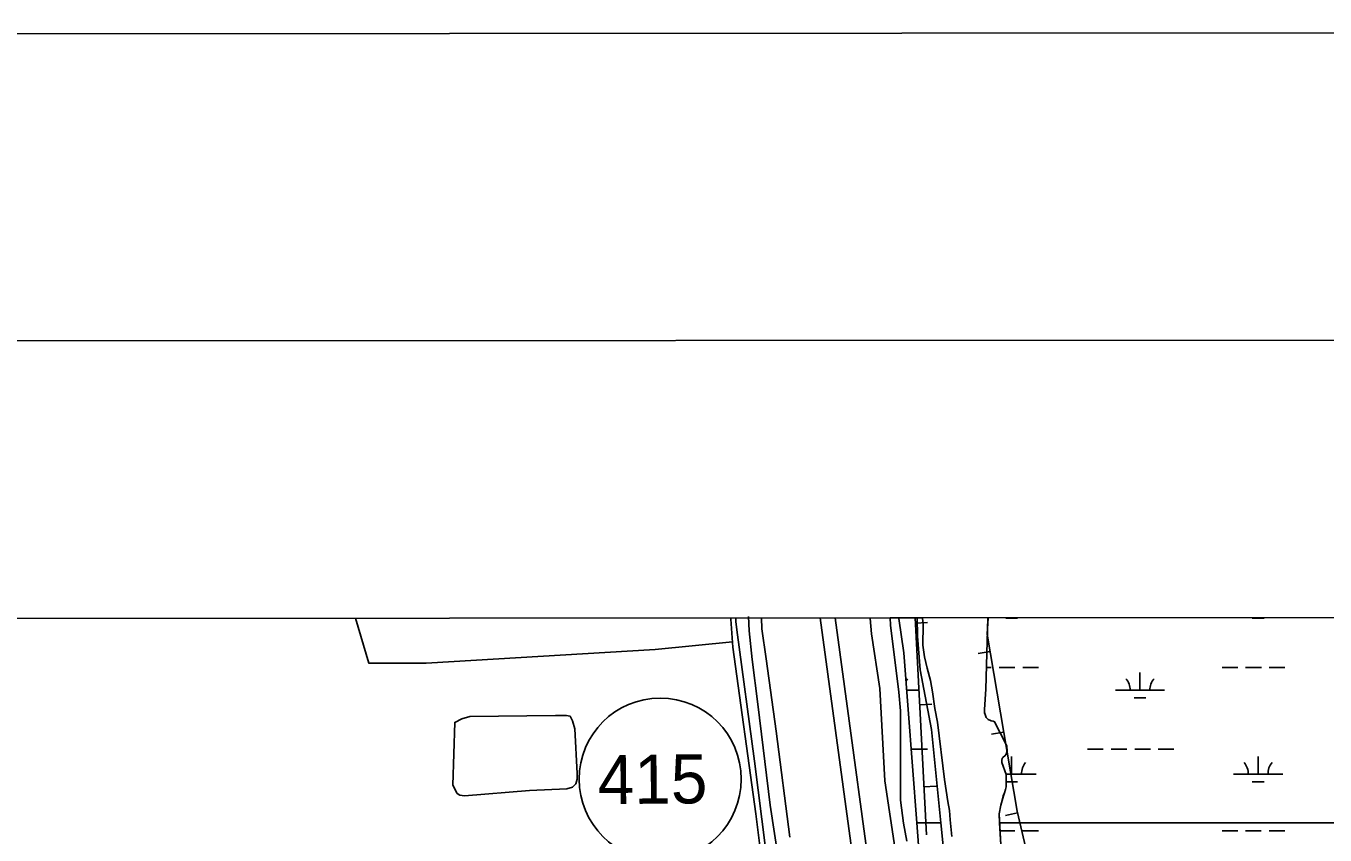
# Model space of a CAD drawing. Extents: x 3281947 to 3319794, y 715894 to 741249.
# Drawn here: x 3291976 to 3294621, y 739019 to 740665 of the extents above; entities that cross this region are included whole.
import ezdxf

# ---------------------------------------------------------------- set-up
doc = ezdxf.new("R2010")
doc.units = 0
for name, color, linetype in [('G-ANNO-NPLT', 7, 'Continuous'), ('V-ANNO-SYMB', 7, 'Continuous'), ('V-BORW-LINE', 7, 'Continuous'), ('V-DTCH-CNTR', 7, 'Continuous'), ('V-GRID-FRAM', 7, 'Continuous'), ('V-LEVE-TOET', 7, 'Continuous'), ('V-ROAD-CNTR', 7, 'Continuous'), ('V-ROAD-IDEN', 7, 'Continuous'), ('V-SITE-VEGE', 7, 'Continuous'), ('V-SURV-LINE', 7, 'Continuous'), ('V-TOPO-SHOR', 7, 'Continuous'), ('V-WETL-SWMP', 7, 'Continuous')]:
    doc.layers.add(name, color=color, linetype=linetype)

msp = doc.modelspace()

# ---------------------------------------------------------------- linework, layer by layer
at = {"layer": 'G-ANNO-NPLT'}
msp.add_lwpolyline([(3282544.2, 716477.2), (3319210.9, 716498.6), (3319196.8, 740665.2), (3282530.2, 740643.9)], close=True, dxfattribs=at)
at = {"layer": 'V-ANNO-SYMB'}
msp.add_lwpolyline([(3285294, 717103.9), (3318377.2, 717123.1), (3318363.9, 740039.7), (3285280.7, 740020.4), (3285294, 717103.9)], dxfattribs=at)
at = {"layer": 'V-BORW-LINE'}
for p, q in [((3293786.5, 739449.7), (3293811.4, 739451)), ((3293938.8, 739392.4), (3293914.1, 739388.3)), ((3293795.1, 739283.3), (3293820.1, 739284.6)), ((3293966.4, 739228.2), (3293941.8, 739224)), ((3293803.8, 739116.9), (3293828.7, 739118.2)), ((3293994.3, 739063.9), (3293970, 739058.2))]:
    msp.add_line(p, q, dxfattribs=at)
for points in [[(3293785.9, 739460.7), (3293808.9, 739018.8)], [(3293808.9, 739018.8), (3293785.9, 739460.7)], [(3294013.5, 738982.8), (3293993.5, 739067.2), (3293932.9, 739427.6), (3293934.7, 739460.7)], [(3293934.7, 739460.7), (3293932.9, 739427.6), (3293993.5, 739067.2), (3294013.5, 738982.8)]]:
    msp.add_lwpolyline(points, dxfattribs=at)
at = {"layer": 'V-DTCH-CNTR'}
for points in [[(3291851.2, 738680.1), (3292201.5, 738700.7), (3292515.1, 738720.8), (3292753.9, 738735.4), (3292868.1, 738749.9), (3292880.2, 738749.6), (3292899.7, 738743.2), (3292915.8, 738736.3), (3292940.9, 738730.1), (3293230, 738752.2), (3293464.6, 738774), (3293472.9, 738774.8), (3293478.7, 738776.1), (3293483.2, 738777.9), (3293489.3, 738781.9), (3293491.4, 738786.1), (3293493.4, 738791.7), (3293494.4, 738800.9), (3293492.7, 738812.4), (3293462, 739061.4), (3293414.9, 739400.7), (3293410.8, 739457.9), (3293410.8, 739460.4)], [(3293414.1, 739411.7), (3293257.1, 739396.1), (3292790.8, 739368.2), (3292674, 739368.3), (3292646.8, 739460)]]:
    msp.add_lwpolyline(points, dxfattribs=at)
at = {"layer": 'V-GRID-FRAM'}
msp.add_lwpolyline([(3286080.7, 739456.2), (3317564.6, 739474.5), (3317583.1, 721289.3), (3286083.3, 721271), (3286080.7, 739456.2)], dxfattribs=at)
at = {"layer": 'V-LEVE-TOET'}
for points in [[(3293473.1, 739460.5), (3293474, 739438.1), (3293482.5, 739377.3), (3293503.2, 739229.7), (3293530.8, 739013.9)], [(3293768.3, 738836), (3293724.7, 739129.2), (3293714.4, 739316.8), (3293697.3, 739428.1), (3293694.3, 739459.2), (3293694.3, 739460.6)]]:
    msp.add_lwpolyline(points, dxfattribs=at)
at = {"layer": 'V-ROAD-CNTR'}
msp.add_lwpolyline([(3293526.2, 738848.4), (3293491.1, 739079.2), (3293465.9, 739285.2), (3293454, 739375.7), (3293448.3, 739434), (3293447, 739463.3)], dxfattribs=at)
at = {"layer": 'V-ROAD-IDEN'}
msp.add_circle((3293267.1, 739132.4), 165, dxfattribs=at)
at = {"layer": 'V-SITE-VEGE'}
for p, q in [((3293735.5, 739460.6), (3293800.9, 739460.7)), ((3293736.2, 739445.6), (3293735.5, 739460.6)), ((3293753.1, 739309.4), (3293736.2, 739445.6)), ((3293800.9, 739460.7), (3293802.4, 739446.3)), ((3293802.4, 739446.3), (3293802.1, 739405.2)), ((3293934.4, 739460.7), (3293932.8, 739412.6)), ((3295784.5, 739461.8), (3293934.4, 739460.7)), ((3293932.8, 739412.6), (3293930, 739315.6)), ((3293802.1, 739405.2), (3293805.3, 739381.6)), ((3293805.3, 739381.6), (3293810.9, 739358.3)), ((3293810.9, 739358.3), (3293817.2, 739332.9)), ((3293756.6, 739271.6), (3293753.1, 739309.4)), ((3293817.2, 739332.9), (3293821.7, 739309.8)), ((3293821.7, 739309.8), (3293826.4, 739276.2)), ((3293930, 739315.6), (3293927, 739274.4)), ((3293756.6, 739236.1), (3293756.6, 739271.6)), ((3293826.4, 739276.2), (3293831.7, 739248.2)), ((3293927, 739274.4), (3293927.5, 739267.6)), ((3293927.5, 739267.6), (3293928.8, 739263.6)), ((3293928.8, 739263.6), (3293930.9, 739257.6)), ((3293930.9, 739257.6), (3293934.8, 739253.8)), ((3293756.1, 739089.3), (3293756.6, 739236.1)), ((3293831.7, 739248.2), (3293845.9, 739131.5)), ((3293934.8, 739253.8), (3293939.4, 739251.4)), ((3293939.4, 739251.4), (3293941.1, 739250.7)), ((3293941.1, 739250.7), (3293944.9, 739250)), ((3293944.9, 739250), (3293947.7, 739249.3)), ((3293947.7, 739249.3), (3293972.7, 739200.2)), ((3293963.1, 739174.8), (3293962.4, 739170.2)), ((3293964.7, 739176.4), (3293963.1, 739174.8)), ((3293969.7, 739180.4), (3293964.7, 739176.4)), ((3293971.7, 739183), (3293969.7, 739180.4)), ((3293973.4, 739189.4), (3293971.7, 739183)), ((3293972.7, 739200.2), (3293973.4, 739189.4)), ((3293962.4, 739170.2), (3293962.7, 739165.9)), ((3293962.7, 739165.9), (3293971.5, 739142.1)), ((3293845.9, 739131.5), (3293852.4, 739086.9)), ((3293971.5, 739142.1), (3293971.6, 739116.4)), ((3293965.7, 739098.1), (3293961.6, 739084.1)), ((3293968.3, 739104.4), (3293965.7, 739098.1)), ((3293970.1, 739111.4), (3293968.3, 739104.4)), ((3293971.6, 739116.4), (3293970.1, 739111.4)), ((3293762.4, 739042.8), (3293756.1, 739089.3)), ((3293852.4, 739086.9), (3293855.9, 739068.6)), ((3293960.8, 739079.4), (3293956.9, 739062)), ((3293961.6, 739084.1), (3293960.8, 739079.4)), ((3293769.1, 739005.9), (3293762.4, 739042.8)), ((3293855.9, 739068.6), (3293857.5, 739049.5)), ((3293857.5, 739049.5), (3293860.9, 739015.7)), ((3293956.9, 739062), (3293960.4, 738998.8))]:
    msp.add_line(p, q, dxfattribs=at)
msp.add_lwpolyline([(3292853.6, 739103.1), (3292844.6, 739120), (3292848.8, 739247.8), (3292863.3, 739255.4), (3292879.2, 739260.1), (3293053.7, 739261.9), (3293075.9, 739262.2), (3293083.5, 739260.2), (3293088.3, 739251.1), (3293093.5, 739234.7), (3293098.2, 739143.8), (3293098.1, 739132.2), (3293095.6, 739122.6), (3293088.4, 739116), (3293076.8, 739112.7), (3293000.8, 739109.3), (3292868.5, 739098.6), (3292859.4, 739099.7)], close=True, dxfattribs=at)
at = {"layer": 'V-SURV-LINE'}
for points in [[(3293686.6, 738773), (3293592.8, 739460.5)], [(3293623, 739460.6), (3293716.3, 738777)]]:
    msp.add_lwpolyline(points, dxfattribs=at)
at = {"layer": 'V-TOPO-SHOR'}
for points in [[(3293512.3, 738335), (3293514.6, 738407.4), (3293515.8, 738649.5), (3293504.2, 738809.6), (3293459, 739169.2), (3293422.8, 739436), (3293421, 739452.9), (3293421, 739460.4)], [(3293960.4, 738998.8), (3293956.9, 739062), (3293960.8, 739079.4), (3293961.6, 739084.1), (3293965.7, 739098.1), (3293968.3, 739104.4), (3293970.1, 739111.4), (3293971.6, 739116.4), (3293971.6, 739133.8), (3293971.5, 739142.1), (3293962.7, 739165.9), (3293962.4, 739170.2), (3293963.1, 739174.8), (3293964.7, 739176.4), (3293969.7, 739180.4), (3293971.7, 739183), (3293973.4, 739189.4), (3293972.7, 739200.2), (3293947.7, 739249.3), (3293944.9, 739250), (3293941.1, 739250.7), (3293939.4, 739251.4), (3293934.8, 739253.8), (3293930.9, 739257.6), (3293928.8, 739263.6), (3293927.5, 739267.6), (3293927, 739274.4), (3293930, 739315.6), (3293932.8, 739412.6), (3293934.4, 739460.7)]]:
    msp.add_lwpolyline(points, dxfattribs=at)
at = {"layer": 'V-WETL-SWMP'}
for p, q in [((3293753.2, 739460.6), (3293753.1, 739459.6)), ((3293753.1, 739459.6), (3293763.1, 739389.4)), ((3293789.9, 739460.7), (3293753.2, 739460.6)), ((3293790.7, 739423), (3293789.9, 739460.7)), ((3293934.4, 739460.7), (3293932.7, 739412.6)), ((3296814.4, 739462.4), (3293934.4, 739460.7)), ((3293970.5, 739459.8), (3293994.5, 739459.8)), ((3294472.4, 739459.8), (3294496.4, 739459.8)), ((3293796.4, 739354.5), (3293790.7, 739423)), ((3293932.7, 739412.6), (3293929.9, 739315.6)), ((3293763.1, 739389.4), (3293789.7, 739043.4)), ((3293931.2, 739359.8), (3293941.1, 739359.8)), ((3293957.1, 739359.8), (3293989.1, 739359.8)), ((3294005.1, 739359.8), (3294037.1, 739359.8)), ((3294411, 739359.8), (3294443, 739359.8)), ((3294459, 739359.8), (3294491, 739359.8)), ((3294507, 739359.8), (3294539, 739359.8)), ((3293819.5, 739233.1), (3293796.4, 739354.5)), ((3294243.9, 739313.3), (3294243.9, 739349.3)), ((3293769, 739313.3), (3293792, 739313.3)), ((3293929.9, 739315.6), (3293927, 739274.4)), ((3294193.9, 739313.3), (3294293.9, 739313.3)), ((3294231.9, 739297.9), (3294255.9, 739297.9)), ((3293927, 739274.4), (3293927.5, 739267.7)), ((3293927.5, 739267.7), (3293928.8, 739263.6)), ((3293928.8, 739263.6), (3293930.9, 739257.6)), ((3293930.9, 739257.6), (3293934.8, 739253.8)), ((3293838.7, 739043.4), (3293819.5, 739233.1)), ((3293934.8, 739253.8), (3293939.4, 739251.4)), ((3293939.4, 739251.4), (3293941.1, 739250.7)), ((3293941.1, 739250.7), (3293944.9, 739250)), ((3293944.9, 739250), (3293947.7, 739249.3)), ((3293947.7, 739249.3), (3293972.7, 739200.3)), ((3293779.2, 739193.3), (3293811.2, 739193.3)), ((3293963, 739174.8), (3293962.3, 739170.2)), ((3293964.7, 739176.4), (3293963, 739174.8)), ((3293969.7, 739180.4), (3293964.7, 739176.4)), ((3293971.7, 739183), (3293969.7, 739180.4)), ((3293973.4, 739189.5), (3293971.7, 739183)), ((3293972.7, 739200.3), (3293973.4, 739189.5)), ((3293982.5, 739142.5), (3293982.5, 739178.5)), ((3294137.1, 739193.3), (3294169.1, 739193.3)), ((3294185.1, 739193.3), (3294217.1, 739193.3)), ((3294233.1, 739193.3), (3294265.1, 739193.3)), ((3294281.1, 739193.3), (3294313.1, 739193.3)), ((3294484.4, 739142.5), (3294484.4, 739178.5)), ((3293962.3, 739170.2), (3293962.7, 739165.9)), ((3293962.7, 739165.9), (3293971.5, 739142.1)), ((3293971.3, 739142.5), (3294032.5, 739142.5)), ((3293971.5, 739142.1), (3293971.6, 739116.4)), ((3293971.5, 739127.1), (3293994.5, 739127.1)), ((3294434.4, 739142.5), (3294534.4, 739142.5)), ((3294472.4, 739127.1), (3294496.4, 739127.1)), ((3293965.6, 739098.1), (3293961.6, 739084.1)), ((3293968.3, 739104.4), (3293965.6, 739098.1)), ((3293970.1, 739111.4), (3293968.3, 739104.4)), ((3293971.6, 739116.4), (3293970.1, 739111.4)), ((3293960.8, 739079.4), (3293956.9, 739062)), ((3293961.6, 739084.1), (3293960.8, 739079.4)), ((3293789.7, 739043.4), (3293838.7, 739043.4)), ((3293956.9, 739062), (3293957.9, 739043.4)), ((3293957.9, 739043.4), (3297359.6, 739043.4)), ((3293958.8, 739027.1), (3293989, 739027.1)), ((3294005, 739027.1), (3294037, 739027.1)), ((3294410.9, 739027.1), (3294442.9, 739027.1)), ((3294458.9, 739027.1), (3294490.9, 739027.1)), ((3294506.9, 739027.1), (3294538.9, 739027.1))]:
    msp.add_line(p, q, dxfattribs=at)
for points in [[(3293847.5, 738956), (3293838.7, 739043.4), (3293789.7, 739043.4), (3293793.2, 738998.2)], [(3297359.6, 739043.4), (3293957.9, 739043.4), (3293960.4, 738998.8)]]:
    msp.add_lwpolyline(points, dxfattribs=at)
for centre, start, end in [((3293797.3, 739313.8), 139.2282, 147.646), ((3294188.7, 739313.8), 359.2282, 40.7718), ((3294299.2, 739313.8), 139.2282, 180.7718), ((3294037.7, 739143), 139.2282, 180.7718), ((3294429.2, 739143), 359.2282, 40.7718), ((3294539.6, 739143), 139.2282, 180.7718)]:
    msp.add_arc(centre, 35.2, start, end, dxfattribs=at)

# ---------------------------------------------------------------- texts
at = {"layer": 'V-ROAD-IDEN'}
msp.add_text('415', height=100, rotation=0.4943, dxfattribs=at).set_placement((3293140.4, 739081.3))

doc.saveas('drawing.dxf')
